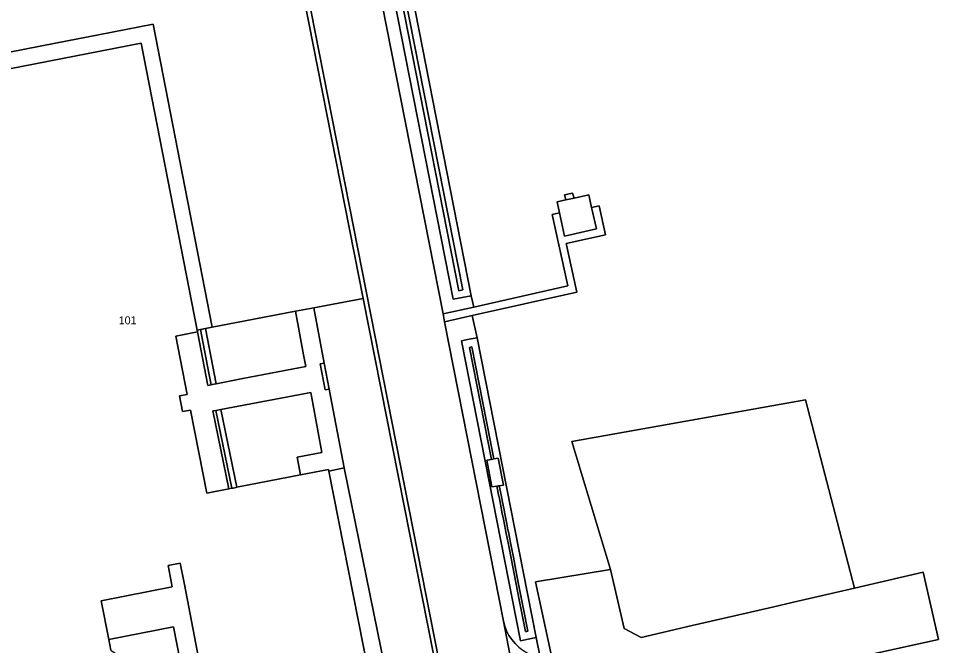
# Model space of a CAD drawing. Extents: x 152881 to 155736, y 382924 to 386919.
# Drawn here: x 154201.8 to 154316.7, y 383322.1 to 383400.4 of the extents above; entities that cross this region are included whole.
import ezdxf

# ---------------------------------------------------------------- set-up
doc = ezdxf.new("R2010")
doc.units = 0
for name, color, linetype in [('IMGEO_Groenvoorziening', 7, 'Continuous'), ('IMGEO_Loofbos', 7, 'Continuous'), ('IMGEO_Oever', 7, 'Continuous'), ('IMGEO_Pand', 7, 'Continuous'), ('IMGEO_Pand_nummerreeks', 7, 'Continuous'), ('IMGEO_Parkeervlak_gesloten', 7, 'Continuous'), ('IMGEO_Rijbaan_lokaal_gesloten', 7, 'Continuous'), ('IMGEO_Rijbaan_lokaal_open', 7, 'Continuous'), ('IMGEO_Terreindeel_gesloten', 7, 'Continuous'), ('IMGEO_Voetpad_gesloten', 7, 'Continuous'), ('IMGEO_Voetpad_open', 7, 'Continuous'), ('IMGEO_Waterloop', 7, 'Continuous')]:
    doc.layers.add(name, color=color, linetype=linetype)

msp = doc.modelspace()

# ---------------------------------------------------------------- linework, layer by layer
at = {"layer": 'IMGEO_Groenvoorziening'}
msp.add_lwpolyline([(154244.83, 383414.15), (154254.81, 383363.47), (154258.66, 383364.33), (154258.34, 383365.74), (154256.08, 383365.31), (154247.15, 383410.64)], dxfattribs=at)
for points in [[(154229.82, 383355.39), (154237.68, 383356.9), (154237.39, 383358.37), (154236.4, 383363.81), (154225.98, 383361.8), (154225.13, 383361.64), (154226.46, 383354.74)], [(154259.07, 383360.49), (154258.45, 383363.26), (154255.01, 383362.49), (154262.37, 383325.11), (154262.53, 383324.49), (154262.75, 383323.89), (154263.05, 383323.33), (154263.4, 383322.8), (154263.81, 383322.31), (154264.27, 383321.87), (154264.78, 383321.49), (154265.33, 383321.17), (154265.91, 383320.91), (154266.52, 383320.72), (154266.96, 383320.63), (154266.44, 383323.08), (154265.46, 383322.86), (154264.49, 383322.65), (154257.11, 383360.11), (154258.09, 383360.3)], [(154225.97, 383354.64), (154226.21, 383354.69), (154226.46, 383354.74), (154225.13, 383361.64), (154224.89, 383361.59), (154224.64, 383361.54), (154224.5, 383361.52), (154225.55, 383356.09), (154225.83, 383354.62)], [(154237.01, 383343.36), (154236.6, 383345.59), (154239.69, 383346.17), (154238.3, 383353.64), (154227.07, 383351.55), (154229.07, 383341.82)], [(154275.75, 383331.58), (154277.43, 383324.18), (154279.58, 383323.09), (154282.94, 383323.87), (154285.4, 383324.44), (154296.13, 383326.91), (154298.59, 383327.48), (154306.22, 383329.23), (154300.1, 383352.74), (154270.91, 383347.54)], [(154227.07, 383351.55), (154227.07, 383351.55), (154226.83, 383351.5), (154226.44, 383351.43), (154228.44, 383341.7), (154228.58, 383341.73), (154228.58, 383341.72), (154228.82, 383341.77), (154229.07, 383341.82)], [(154213.32, 383321.48), (154219.91, 383317.04), (154221.99, 383320.17), (154221.15, 383324.41), (154213.05, 383322.82)]]:
    msp.add_lwpolyline(points, close=True, dxfattribs=at)
at = {"layer": 'IMGEO_Loofbos'}
for points in [[(154250.48, 383405.64), (154258.34, 383365.74), (154258.66, 383364.33), (154270.4, 383366.97), (154268.45, 383375.86), (154269.38, 383376.07), (154269.07, 383377.45), (154270.16, 383377.7), (154269.99, 383378.33), (154270.98, 383378.55), (154271.18, 383377.93), (154273.03, 383378.35), (154273.38, 383376.76), (154274.31, 383376.97), (154275.1, 383373.36), (154270.21, 383372.26), (154271.55, 383366.2), (154258.45, 383363.26), (154259.07, 383360.49), (154266.44, 383323.08), (154266.96, 383320.63)], [(154268.42, 383320.56), (154266.37, 383330.01), (154275.75, 383331.58), (154270.91, 383347.54), (154300.1, 383352.74), (154306.22, 383329.23), (154314.81, 383331.21), (154316.73, 383322.82), (154306.11, 383320.51)]]:
    msp.add_lwpolyline(points, dxfattribs=at)
at = {"layer": 'IMGEO_Oever'}
for points in [[(154249.42, 383406.37), (154257.28, 383366.46), (154256.79, 383366.36), (154248.03, 383410.83)], [(154247.15, 383410.64), (154256.08, 383365.31), (154258.34, 383365.74), (154250.48, 383405.64)]]:
    msp.add_lwpolyline(points, dxfattribs=at)
for points in [[(154259.07, 383360.49), (154258.09, 383360.3), (154257.11, 383360.11), (154264.49, 383322.65), (154265.46, 383322.86), (154266.44, 383323.08)], [(154260.27, 383345.2), (154260.89, 383345.31), (154258.13, 383359.29), (154258.28, 383359.32), (154258.43, 383359.35), (154261.18, 383345.36), (154261.18, 383345.36), (154261.7, 383345.45), (154262.35, 383342.1), (154261.84, 383342.02), (154261.92, 383341.63), (154262.11, 383340.68), (154262.2, 383340.18), (154262.48, 383338.8), (154262.49, 383338.73), (154262.54, 383338.49), (154262.78, 383337.28), (154262.93, 383336.51), (154262.98, 383336.25), (154263.15, 383335.4), (154263.25, 383334.88), (154263.6, 383333.11), (154263.92, 383331.48), (154264.26, 383329.72), (154265.12, 383325.37), (154265.17, 383325.13), (154265.42, 383323.88), (154265.27, 383323.84), (154265.12, 383323.81), (154264.34, 383327.79), (154263.96, 383329.72), (154263.06, 383334.27), (154262.94, 383334.88), (154262.71, 383336.05), (154262.67, 383336.25), (154262.62, 383336.51), (154262.36, 383337.84), (154262.18, 383338.73), (154262.17, 383338.8), (154261.81, 383340.63), (154261.8, 383340.68), (154261.55, 383341.96), (154261.55, 383341.97), (154260.91, 383341.86)]]:
    msp.add_lwpolyline(points, close=True, dxfattribs=at)
at = {"layer": 'IMGEO_Pand'}
for points in [[(154245.44, 383318.95), (154240.55, 383343.84), (154240.51, 383344.04), (154237.01, 383343.36), (154229.07, 383341.82), (154228.82, 383341.77), (154228.58, 383341.72), (154228.58, 383341.73), (154228.44, 383341.7), (154228.05, 383341.62), (154225.29, 383341.09), (154223.24, 383351.46), (154222.26, 383351.27), (154221.88, 383353.23), (154222.86, 383353.42), (154221.43, 383360.69), (154224.13, 383361.22), (154224.09, 383361.44), (154217.09, 383397.28), (154187.16, 383391.43)], [(154213.32, 383321.48), (154213.05, 383322.82), (154212.1, 383327.66), (154220.97, 383329.39), (154220.47, 383332.05), (154221.98, 383332.33), (154222.52, 383329.69), (154226.21, 383310.31)]]:
    msp.add_lwpolyline(points, dxfattribs=at)
msp.add_lwpolyline([(154273.38, 383376.76), (154273.03, 383378.35), (154271.18, 383377.93), (154270.16, 383377.7), (154269.07, 383377.45), (154269.38, 383376.07), (154270.01, 383373.18), (154273.97, 383374.08)], close=True, dxfattribs=at)
at = {"layer": 'IMGEO_Parkeervlak_gesloten'}
msp.add_lwpolyline([(154238.65, 383364.22), (154239.96, 383357.33), (154240.58, 383354.08), (154242.45, 383344.25), (154247.53, 383319.34), (154247.63, 383319.36), (154248.32, 383319.51), (154249.02, 383319.59), (154249.73, 383319.59), (154250.43, 383319.51), (154251.12, 383319.35), (154251.79, 383319.12), (154252.43, 383318.81), (154253.03, 383318.44), (154253.59, 383318.01), (154254.1, 383317.51), (154254.36, 383317.2), (154244.84, 383365.41)], close=True, dxfattribs=at)
at = {"layer": 'IMGEO_Rijbaan_lokaal_gesloten'}
for points in [[(154177.92, 383401.47), (154155.4, 383395.53), (154164.47, 383349.03), (154171.29, 383350.34), (154171.81, 383350.46), (154174.12, 383338.68), (154173.61, 383338.55), (154166.76, 383337.24), (154173.17, 383304.39), (154193.13, 383308.25), (154193.23, 383308.27), (154183.28, 383359.76), (154191.1, 383361.24), (154184.88, 383393.05), (154206.38, 383397.26), (154211.76, 383398.31), (154218.59, 383399.65), (154225.98, 383361.8), (154236.4, 383363.81), (154238.65, 383364.22), (154244.84, 383365.41), (154235.21, 383414.2)], [(154235.61, 383414.95), (154254.82, 383317.48), (154255.2, 383316.95), (154255.52, 383316.39), (154255.79, 383315.8), (154256, 383315.18), (154256.66, 383311.83), (154259.53, 383297.34), (154264.59, 383271.73), (154264.68, 383271.04), (154267.52, 383256.02), (154267.53, 383256.01), (154267.7, 383255.79), (154267.84, 383254.33), (154286.74, 383157.13)], [(154283.16, 383219.21), (154279.58, 383237.23), (154266.05, 383306.02), (154262.37, 383325.11), (154255.01, 383362.49), (154254.81, 383363.47), (154244.83, 383414.15)], [(154306.11, 383320.51), (154316.73, 383322.82), (154314.81, 383331.21), (154306.22, 383329.23), (154298.59, 383327.48), (154296.13, 383326.91), (154285.4, 383324.44), (154282.94, 383323.87), (154279.58, 383323.09), (154277.43, 383324.18), (154275.75, 383331.58), (154266.37, 383330.01), (154268.42, 383320.56)], [(154264.27, 383321.87), (154263.81, 383322.31), (154263.4, 383322.8), (154263.05, 383323.33), (154262.75, 383323.89), (154262.53, 383324.49), (154262.37, 383325.11), (154266.05, 383306.02)]]:
    msp.add_lwpolyline(points, dxfattribs=at)
at = {"layer": 'IMGEO_Rijbaan_lokaal_open'}
for points in [[(154197.97, 383295.22), (154245.99, 383304.61), (154252.35, 383305.88), (154252.97, 383306.04), (154253.58, 383306.28), (154254.15, 383306.59), (154254.69, 383306.97), (154255.17, 383307.41), (154255.6, 383307.91), (154255.96, 383308.45), (154256.26, 383309.03), (154256.48, 383309.65), (154256.63, 383310.29), (154256.7, 383310.94), (154256.7, 383311.59), (154256.66, 383311.83), (154256, 383315.18), (154255.79, 383315.8), (154255.52, 383316.39), (154255.2, 383316.95), (154254.82, 383317.48), (154235.61, 383414.95)], [(154235.21, 383414.2), (154244.84, 383365.41), (154254.36, 383317.2)]]:
    msp.add_lwpolyline(points, dxfattribs=at)
for points in [[(154224.13, 383361.22), (154225.44, 383354.54), (154225.83, 383354.62), (154225.55, 383356.09), (154224.5, 383361.52), (154224.09, 383361.44)], [(154228.44, 383341.7), (154226.44, 383351.43), (154226.05, 383351.35), (154228.05, 383341.62)]]:
    msp.add_lwpolyline(points, close=True, dxfattribs=at)
at = {"layer": 'IMGEO_Terreindeel_gesloten'}
msp.add_lwpolyline([(154261.55, 383341.97), (154261.69, 383341.99), (154261.84, 383342.02), (154262.35, 383342.1), (154261.7, 383345.45), (154261.18, 383345.36), (154261.04, 383345.34), (154260.89, 383345.31), (154260.27, 383345.2), (154260.91, 383341.86)], close=True, dxfattribs=at)
at = {"layer": 'IMGEO_Voetpad_gesloten'}
msp.add_lwpolyline([(154239.96, 383357.33), (154239.47, 383357.24), (154240.09, 383353.98), (154240.58, 383354.08)], close=True, dxfattribs=at)
at = {"layer": 'IMGEO_Voetpad_open'}
for points in [[(154218.59, 383399.65), (154211.76, 383398.31), (154206.38, 383397.26), (154184.88, 383393.05), (154191.1, 383361.24), (154183.28, 383359.76), (154193.23, 383308.27), (154195.1, 383308.62), (154190.03, 383334.65), (154192.47, 383335.15), (154188.73, 383354.3), (154186.27, 383353.83), (154185.39, 383358.32), (154193.33, 383359.86), (154187.16, 383391.43), (154217.09, 383397.28), (154224.09, 383361.44), (154224.5, 383361.52), (154224.64, 383361.54), (154224.89, 383361.59), (154225.13, 383361.64), (154225.98, 383361.8)], [(154271.18, 383377.93), (154270.98, 383378.55), (154269.99, 383378.33), (154270.16, 383377.7)], [(154269.38, 383376.07), (154268.45, 383375.86), (154270.4, 383366.97), (154258.66, 383364.33), (154254.81, 383363.47), (154255.01, 383362.49), (154258.45, 383363.26), (154271.55, 383366.2), (154270.21, 383372.26), (154275.1, 383373.36), (154274.31, 383376.97), (154273.38, 383376.76), (154273.97, 383374.08), (154270.01, 383373.18)], [(154239.96, 383357.33), (154238.65, 383364.22), (154236.4, 383363.81), (154237.39, 383358.37), (154237.68, 383356.9), (154229.82, 383355.39), (154226.46, 383354.74), (154226.21, 383354.69), (154225.97, 383354.64), (154225.83, 383354.62), (154225.44, 383354.54), (154224.13, 383361.22), (154221.43, 383360.69), (154222.86, 383353.42), (154221.88, 383353.23), (154222.26, 383351.27), (154223.24, 383351.46), (154225.29, 383341.09), (154228.05, 383341.62), (154226.05, 383351.35), (154226.44, 383351.43), (154226.83, 383351.5), (154227.07, 383351.55), (154227.07, 383351.55), (154238.3, 383353.64), (154239.69, 383346.17), (154236.6, 383345.59), (154237.01, 383343.36), (154240.51, 383344.04), (154240.55, 383343.84), (154242.45, 383344.25), (154240.58, 383354.08), (154240.09, 383353.98), (154239.47, 383357.24)], [(154249.12, 383311.86), (154247.53, 383319.34), (154242.45, 383344.25), (154240.55, 383343.84), (154245.44, 383318.95), (154245.48, 383318.73), (154244.94, 383318.61), (154245.85, 383313.84), (154233.15, 383311.37), (154232.96, 383312.35), (154231.21, 383312.01), (154231.4, 383311.03), (154226.27, 383310.02), (154224.06, 383309.59), (154224.56, 383307.05), (154224.77, 383307.09), (154244.77, 383311.01)], [(154224.06, 383309.59), (154226.27, 383310.02), (154226.21, 383310.31), (154222.52, 383329.69), (154221.98, 383332.33), (154220.47, 383332.05), (154220.97, 383329.39), (154212.1, 383327.66), (154213.05, 383322.82), (154221.15, 383324.41), (154221.99, 383320.17), (154222.09, 383319.61), (154222.64, 383316.83), (154224, 383309.88)]]:
    msp.add_lwpolyline(points, close=True, dxfattribs=at)
at = {"layer": 'IMGEO_Waterloop'}
msp.add_lwpolyline([(154248.03, 383410.83), (154256.79, 383366.36), (154257.28, 383366.46), (154249.42, 383406.37)], dxfattribs=at)
for points in [[(154261.18, 383345.36), (154261.18, 383345.36), (154258.43, 383359.35), (154258.28, 383359.32), (154258.13, 383359.29), (154260.89, 383345.31), (154261.04, 383345.34)], [(154265.42, 383323.88), (154265.17, 383325.13), (154265.12, 383325.37), (154264.26, 383329.72), (154263.92, 383331.48), (154263.6, 383333.11), (154263.25, 383334.88), (154263.15, 383335.4), (154262.98, 383336.25), (154262.93, 383336.51), (154262.78, 383337.28), (154262.54, 383338.49), (154262.49, 383338.73), (154262.48, 383338.8), (154262.2, 383340.18), (154262.11, 383340.68), (154261.92, 383341.63), (154261.84, 383342.02), (154261.69, 383341.99), (154261.55, 383341.97), (154261.55, 383341.96), (154261.8, 383340.68), (154261.81, 383340.63), (154262.17, 383338.8), (154262.18, 383338.73), (154262.36, 383337.84), (154262.62, 383336.51), (154262.67, 383336.25), (154262.71, 383336.05), (154262.94, 383334.88), (154263.06, 383334.27), (154263.96, 383329.72), (154264.34, 383327.79), (154265.12, 383323.81), (154265.27, 383323.84)]]:
    msp.add_lwpolyline(points, close=True, dxfattribs=at)

# ---------------------------------------------------------------- texts
at = {"layer": 'IMGEO_Pand_nummerreeks'}
msp.add_text('101', height=1, dxfattribs=at).set_placement((154214.29, 383362.17))

doc.saveas('drawing.dxf')
